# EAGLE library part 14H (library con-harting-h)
CONNECTOR
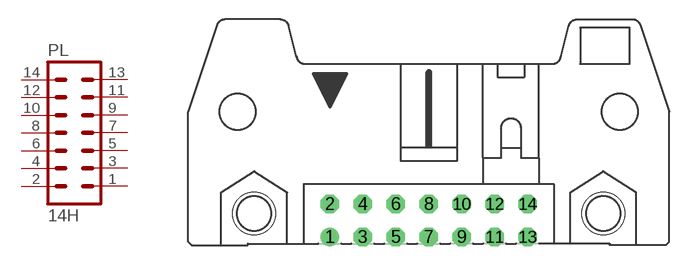
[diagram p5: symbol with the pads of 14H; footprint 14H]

Designator prefix PL

## 14H (OC_FARNELL: unknown; OC_NEWARK: unknown)  [14H]
1  1  pas
2  2  pas
3  3  pas
4  4  pas
5  5  pas
6  6  pas
7  7  pas
8  8  pas
9  9  pas
10  10  pas
11  11  pas
12  12  pas
13  13  pas
14  14  pas

## Footprint 14H (pad centres in mm)
CONNECTOR
drill 0.914 round: 1 -7.62,-1.27
drill 0.914 octagon: 2 -7.62,1.27; 3 -5.08,-1.27; 4 -5.08,1.27; 5 -2.54,-1.27; 6 -2.54,1.27; 7 0,-1.27; 8 0,1.27; 9 2.54,-1.27; 10 2.54,1.27; 11 5.08,-1.27; 12 5.08,1.27; 13 7.62,-1.27; 14 7.62,1.27
hole 3.302 at -13.462,0.533
hole 3.302 at 13.462,0.533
